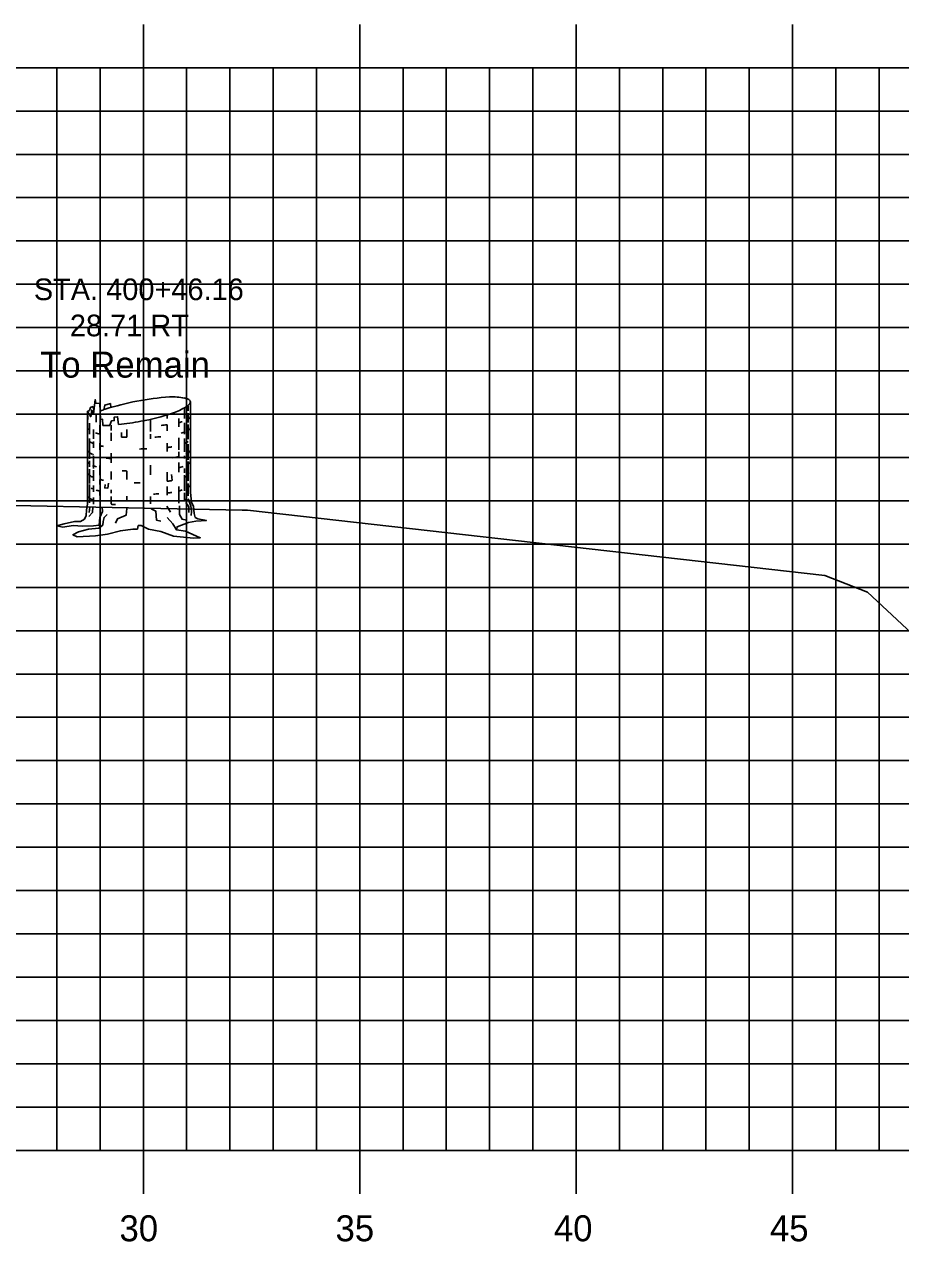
# Model space of a CAD drawing. Extents: x -161 to 764, y 111 to 210.
# Drawn here: x 181.42 to 201.67, y 125.06 to 153.17 of the extents above; entities that cross this region are included whole.
import ezdxf

# ---------------------------------------------------------------- set-up
doc = ezdxf.new("R2010")
doc.units = 0
for name, color, linetype in [('D_Text_Monospaced', 7, 'Continuous'), ('D_Text_Standard', 7, 'Continuous'), ('H_V ANNOTATION', 7, 'Continuous'), ('MAJOR', 7, 'Continuous'), ('MINOR', 7, 'Continuous'), ('S_Roadway_Centerline', 7, 'Continuous'), ('S_Trees_Decid_Pay', 7, 'Continuous')]:
    doc.layers.add(name, color=color, linetype=linetype)

msp = doc.modelspace()

# ---------------------------------------------------------------- linework, layer by layer
at = {"layer": 'MAJOR'}
for p, q in [((184.168, 153.171), (184.168, 152.169)), ((189.168, 153.171), (189.168, 152.169)), ((194.168, 153.171), (194.168, 152.169)), ((199.168, 153.171), (199.168, 152.169)), ((84.168, 152.169), (224.168, 152.169)), ((84.168, 152.169), (224.168, 152.169)), ((184.168, 127.169), (184.168, 152.169)), ((189.168, 127.169), (189.168, 152.169)), ((194.168, 127.169), (194.168, 152.169)), ((199.168, 127.169), (199.168, 152.169)), ((84.168, 147.169), (224.168, 147.169)), ((84.168, 142.169), (224.168, 142.169)), ((84.168, 137.169), (224.168, 137.169)), ((84.168, 132.169), (224.168, 132.169)), ((84.168, 127.169), (224.168, 127.169)), ((84.168, 127.169), (224.168, 127.169)), ((184.168, 126.167), (184.168, 127.169)), ((189.168, 126.167), (189.168, 127.169)), ((194.168, 126.167), (194.168, 127.169)), ((199.168, 126.167), (199.168, 127.169))]:
    msp.add_line(p, q, dxfattribs=at)
at = {"layer": 'MINOR'}
for p, q in [((182.168, 127.169), (182.168, 152.169)), ((183.168, 127.169), (183.168, 152.169)), ((185.168, 127.169), (185.168, 152.169)), ((186.168, 127.169), (186.168, 152.169)), ((187.168, 127.169), (187.168, 152.169)), ((188.168, 127.169), (188.168, 152.169)), ((190.168, 127.169), (190.168, 152.169)), ((191.168, 127.169), (191.168, 152.169)), ((192.168, 127.169), (192.168, 152.169)), ((193.168, 127.169), (193.168, 152.169)), ((195.168, 127.169), (195.168, 152.169)), ((196.168, 127.169), (196.168, 152.169)), ((197.168, 127.169), (197.168, 152.169)), ((198.168, 127.169), (198.168, 152.169)), ((200.168, 127.169), (200.168, 152.169)), ((201.168, 127.169), (201.168, 152.169)), ((84.168, 151.169), (224.168, 151.169)), ((84.168, 150.169), (224.168, 150.169)), ((84.168, 149.169), (224.168, 149.169)), ((84.168, 148.169), (224.168, 148.169)), ((84.168, 146.169), (224.168, 146.169)), ((84.168, 145.169), (224.168, 145.169)), ((84.168, 144.169), (224.168, 144.169)), ((84.168, 143.169), (224.168, 143.169)), ((84.168, 141.169), (224.168, 141.169)), ((84.168, 140.169), (224.168, 140.169)), ((84.168, 139.169), (224.168, 139.169)), ((84.168, 138.169), (224.168, 138.169)), ((84.168, 136.169), (224.168, 136.169)), ((84.168, 135.169), (224.168, 135.169)), ((84.168, 134.169), (224.168, 134.169)), ((84.168, 133.169), (224.168, 133.169)), ((84.168, 131.169), (224.168, 131.169)), ((84.168, 130.169), (224.168, 130.169)), ((84.168, 129.169), (224.168, 129.169)), ((84.168, 128.169), (224.168, 128.169))]:
    msp.add_line(p, q, dxfattribs=at)
at = {"layer": 'S_Roadway_Centerline'}
msp.add_lwpolyline([(152.685, 140.854), (168.169, 142.293), (172.399, 142.133), (178.178, 142.122), (186.449, 141.953), (186.572, 141.953), (199.915, 140.445), (200.903, 140.058), (203.287, 137.833), (209.093, 136.316), (210.852, 135.055), (224.168, 133.439)], dxfattribs=at)
at = {"layer": 'S_Trees_Decid_Pay'}
for p, q in [((185.121, 144.319), (185.121, 144.066)), ((185.201, 144.364), (185.201, 144.243)), ((182.927, 143.96), (182.927, 143.706)), ((183.077, 144.16), (183.077, 143.986)), ((184.333, 144.051), (184.333, 143.771)), ((184.716, 144.152), (184.716, 144.066)), ((184.989, 144.066), (184.989, 143.874)), ((185.121, 143.969), (185.121, 143.706)), ((185.201, 144.191), (185.201, 143.977)), ((185.201, 143.932), (185.201, 143.594)), ((183.013, 143.814), (183.013, 143.603)), ((183.161, 143.912), (183.161, 143.707)), ((183.422, 143.914), (183.422, 143.794)), ((183.422, 143.742), (183.422, 143.557)), ((183.661, 143.642), (183.666, 143.749)), ((183.787, 143.814), (183.787, 143.635)), ((184.333, 143.706), (184.333, 143.603)), ((184.716, 143.925), (184.716, 143.786)), ((182.927, 143.608), (182.927, 143.139)), ((183.013, 143.537), (183.013, 143.389)), ((183.161, 143.5), (183.161, 143.345)), ((184.716, 143.5), (184.716, 143.308)), ((184.989, 143.623), (184.989, 143.345)), ((185.121, 143.608), (185.121, 143.3)), ((185.201, 143.477), (185.201, 143.116)), ((182.927, 143.088), (182.927, 142.954)), ((183.013, 143.211), (183.013, 142.911)), ((183.422, 143.271), (183.422, 143.043)), ((184.989, 143.3), (184.989, 143.191)), ((185.121, 143.211), (185.121, 143.145)), ((182.927, 142.896), (182.927, 142.571)), ((183.013, 142.874), (183.013, 142.631)), ((183.161, 142.982), (183.161, 142.763)), ((183.422, 142.845), (183.422, 142.66)), ((183.787, 142.856), (183.787, 142.66)), ((184.333, 142.991), (184.333, 142.771)), ((184.716, 142.828), (184.716, 142.62)), ((184.989, 143.057), (184.989, 142.828)), ((185.121, 142.911), (185.121, 142.814)), ((185.201, 143.08), (185.201, 142.631)), ((182.927, 142.542), (182.927, 142.122)), ((183.161, 142.663), (183.161, 142.542)), ((185.121, 142.763), (185.121, 142.402)), ((185.201, 142.565), (185.201, 142.283)), ((183.013, 142.52), (183.013, 142.379)), ((183.013, 142.248), (183.013, 142.091)), ((183.161, 142.391), (183.161, 142.293)), ((183.422, 142.425), (183.422, 142.348)), ((183.422, 142.271), (183.422, 142.097)), ((183.787, 142.276), (183.787, 142.173)), ((184.333, 142.271), (184.333, 142.097)), ((184.716, 142.499), (184.716, 142.299)), ((184.989, 142.499), (184.989, 142.116)), ((185.121, 142.351), (185.121, 142.184)), ((182.93, 142.019), (182.916, 141.902)), ((184.712, 142.042), (184.792, 141.91))]:
    msp.add_line(p, q, dxfattribs=at)
for points in [[(183.233, 143.907), (183.225, 144.051), (183.18, 144.043), (183.165, 144.418), (183.071, 144.426), (183.056, 144.506), (183.019, 144.169), (182.974, 144.263), (182.953, 144.109), (182.876, 144.234), (182.882, 144.045)], [(182.876, 144.234), (182.876, 142.097), (182.856, 141.956), (182.85, 141.83), (182.807, 141.743), (182.714, 141.694), (182.579, 141.694), (182.335, 141.638), (182.168, 141.589), (182.311, 141.558), (182.548, 141.595), (182.758, 141.583), (183.019, 141.589), (183.143, 141.607), (183.173, 141.564), (183.235, 141.607), (183.136, 141.54), (182.901, 141.515), (182.671, 141.453), (182.541, 141.383), (182.64, 141.339), (183.062, 141.358), (183.34, 141.402), (183.639, 141.478), (183.925, 141.515), (184.03, 141.515), (184.048, 141.595), (184.117, 141.601), (184.283, 141.515), (184.569, 141.459), (184.868, 141.352), (185.327, 141.303), (185.481, 141.315), (185.14, 141.465), (184.936, 141.496), (184.948, 141.57), (185.208, 141.669), (185.383, 141.7), (185.624, 141.712), (185.426, 141.75), (185.364, 141.786), (185.34, 141.873), (185.327, 142.042), (185.282, 142.128), (185.254, 142.369), (185.254, 144.455)], [(182.876, 144.234), (182.922, 144.257), (182.945, 144.323), (182.997, 144.346), (183.03, 144.271)], [(183.255, 144.273), (183.276, 144.381), (183.408, 144.412), (183.415, 144.324)], [(183.394, 143.912), (183.431, 144.015), (183.497, 144.021), (183.497, 144.103), (183.571, 144.109), (183.596, 143.929)], [(183.285, 142.542), (183.276, 142.468), (183.35, 142.462), (183.365, 142.579)], [(184.83, 142.634), (184.829, 142.711), (184.821, 142.777)], [(182.997, 142.027), (182.99, 141.902), (182.908, 141.807)], [(183.143, 141.607), (183.161, 141.786), (183.223, 141.923), (183.216, 142.023)], [(183.785, 141.99), (183.768, 141.836), (183.571, 141.755), (183.525, 141.652)], [(184.351, 141.982), (184.454, 141.931), (184.468, 141.725), (184.571, 141.696)], [(185.006, 142.056), (185.006, 141.851), (185.063, 141.741), (185.161, 141.725)], [(185.146, 142.13), (185.218, 142.027), (185.218, 141.902)], [(185.203, 142.211), (185.264, 142.05), (185.277, 141.925), (185.27, 141.828)], [(183.334, 141.855), (183.26, 141.786), (183.241, 141.688), (183.235, 141.607)], [(184.936, 141.496), (184.85, 141.638), (184.718, 141.78)]]:
    msp.add_lwpolyline(points, dxfattribs=at)
for centre, radius, start, end in [((185.166, 138.453), 6.126, 93.6944, 100.7779), ((184.855, 143.27), 1.299, 78.2779, 93.6944), ((185.022, 144.073), 0.48, 69.9843, 78.2779), ((185.13, 144.369), 0.164, 55.7779, 69.9843), ((185.162, 144.416), 0.107, 45.9547, 55.7779), ((185.192, 144.447), 0.0645, 33.2779, 45.9547), ((183.686, 143.047), 1.299, 107.8613, 113.3069), ((185.166, 138.453), 6.126, 100.7779, 107.8613), ((184.445, 145.428), 1.299, 287.8613, 303.2779), ((184.894, 144.743), 0.48, 303.2779, 311.5714), ((185.104, 144.507), 0.164, 311.5714, 325.7779), ((185.151, 144.475), 0.107, 325.7779, 335.6011), ((185.2, 144.452), 0.0544, 22.46, 33.2779), ((185.19, 144.457), 0.0645, 335.6011, 348.2779), ((185.207, 144.455), 0.0467, 10.7779, 22.46), ((185.207, 144.455), 0.0467, 359.0957, 10.7779), ((185.199, 144.455), 0.0544, 348.2779, 359.0957), ((182.964, 150.022), 6.126, 275.9147, 280.7779), ((182.964, 150.022), 6.126, 280.7779, 287.8613), ((184.642, 145.217), 1.292, 285.5651, 289.0916), ((185.114, 144.198), 0.166, 301.67, 315), ((185.155, 144.157), 0.109, 315, 324.8263), ((185.19, 144.132), 0.0657, 324.8263, 337.5), ((185.2, 144.128), 0.0554, 337.5, 348.3185), ((182.924, 143.866), 0.0476, 180, 191.6815), ((182.932, 143.868), 0.0554, 191.6815, 202.5), ((182.941, 143.872), 0.0657, 202.5, 215.1737), ((182.977, 143.897), 0.109, 215.1737, 225), ((183.018, 143.937), 0.166, 225, 239.1924), ((183.489, 144.956), 1.292, 250.6119, 255.2856), ((183.275, 145.206), 1.299, 268.1289, 273.6944), ((182.964, 150.022), 6.126, 273.6944, 274.0246), ((184.065, 149.544), 5.916, 273.5382, 274.8924), ((184.066, 149.805), 5.916, 274.9514, 276.3087), ((184.641, 144.956), 1.292, 288.0829, 292.5), ((184.95, 144.21), 0.484, 297.4162, 300.8076), ((185.113, 143.937), 0.166, 300.8076, 315), ((185.154, 143.897), 0.109, 315, 324.8263), ((185.189, 143.872), 0.0657, 324.8263, 337.5), ((185.199, 143.868), 0.0554, 337.5, 348.3185), ((183.018, 143.674), 0.166, 237.0378, 239.1924), ((183.18, 143.947), 0.484, 239.1924, 247.5), ((183.489, 144.693), 1.292, 247.5, 248.3537), ((183.489, 144.693), 1.292, 255.2856, 259.2632), ((184.065, 149.544), 5.916, 266.0776, 267.3043), ((184.065, 149.281), 5.916, 270.1162, 271.7708), ((184.065, 149.281), 5.916, 276.3183, 277.1546), ((184.641, 144.693), 1.292, 277.1546, 278.3662), ((184.641, 144.693), 1.292, 291.8071, 292.5), ((184.95, 143.947), 0.484, 292.5, 300.8076), ((185.113, 143.674), 0.166, 300.8076, 301.6001), ((182.924, 143.345), 0.0476, 180, 191.6815), ((182.924, 143.088), 0.0476, 180, 191.6815), ((182.932, 143.347), 0.0554, 191.6815, 202.5), ((182.941, 143.351), 0.0657, 202.5, 215.1737), ((182.977, 143.376), 0.109, 215.1737, 225), ((183.018, 143.416), 0.166, 225, 239.1924), ((183.18, 143.689), 0.484, 239.1924, 245.7724), ((183.489, 144.435), 1.292, 247.5, 248.4842), ((183.489, 144.435), 1.292, 261.8726, 262.8454), ((184.065, 149.023), 5.916, 262.8454, 263.7595), ((184.641, 144.435), 1.292, 279.2565, 285.6105), ((184.95, 143.689), 0.484, 294.6372, 300.8076), ((185.113, 143.416), 0.166, 300.8076, 315), ((185.154, 143.376), 0.109, 315, 324.8263), ((185.189, 143.351), 0.0657, 324.8263, 337.5), ((185.199, 143.347), 0.0554, 337.5, 348.3185), ((182.924, 142.822), 0.0476, 180, 191.6815), ((182.932, 143.089), 0.0554, 191.6815, 202.5), ((182.932, 142.824), 0.0554, 191.6815, 202.5), ((182.941, 143.093), 0.0657, 202.5, 215.1737), ((182.941, 142.828), 0.0657, 202.5, 215.1737), ((182.977, 143.118), 0.109, 215.1737, 225), ((183.018, 143.159), 0.166, 225, 239.1924), ((183.489, 144.178), 1.292, 247.5, 251.799), ((184.065, 148.766), 5.916, 266.2721, 267.3043), ((184.641, 144.178), 1.292, 285.6105, 290.1001), ((185.113, 143.159), 0.166, 302.0694, 315), ((185.154, 143.118), 0.109, 315, 324.8263), ((185.189, 143.093), 0.0657, 324.8263, 337.5), ((185.199, 143.089), 0.0554, 337.5, 348.3185), ((185.199, 142.824), 0.0554, 337.5, 348.3185), ((182.977, 142.853), 0.109, 215.1737, 225), ((183.018, 142.893), 0.166, 225, 239.1924), ((183.18, 143.166), 0.484, 239.1924, 247.5), ((183.489, 143.913), 1.292, 247.5, 248.3537), ((183.489, 143.913), 1.292, 255.2856, 259.2463), ((184.065, 148.5), 5.916, 268.9206, 270), ((184.065, 148.5), 5.916, 270, 270.2757), ((184.065, 148.5), 5.916, 276.3183, 277.1546), ((184.641, 143.913), 1.292, 277.1546, 278.3795), ((184.95, 143.166), 0.484, 292.5, 300.8076), ((185.113, 142.893), 0.166, 300.8076, 302.0694), ((185.189, 142.556), 0.0657, 324.8263, 337.5), ((185.199, 142.552), 0.0554, 337.5, 348.3185), ((182.924, 142.293), 0.0476, 180, 191.6815), ((182.932, 142.295), 0.0554, 191.6815, 202.5), ((182.941, 142.299), 0.0657, 202.5, 215.1737), ((182.977, 142.324), 0.109, 215.1737, 225), ((183.018, 142.364), 0.166, 225, 239.1924), ((183.18, 142.894), 0.484, 242.734, 247.5), ((183.489, 143.641), 1.292, 251.3664, 255.2856), ((184.065, 148.229), 5.916, 273.2637, 274.461), ((184.065, 148.229), 5.916, 276.3183, 277.1546), ((184.641, 143.641), 1.292, 277.1546, 278.3662), ((184.641, 143.641), 1.292, 285.6105, 289.1534), ((185.113, 142.621), 0.166, 302.0694, 315), ((185.154, 142.581), 0.109, 315, 324.8263), ((183.18, 142.637), 0.484, 239.1924, 247.5), ((183.489, 143.383), 1.292, 247.5, 248.3537), ((184.065, 147.971), 5.916, 263.7831, 264.7655), ((184.65, 143.387), 1.292, 291.3696, 292.0604), ((184.95, 142.637), 0.484, 292.5, 296.5499)]:
    msp.add_arc(centre, radius, start, end, dxfattribs=at)

# ---------------------------------------------------------------- texts
at = {"layer": 'D_Text_Monospaced'}
for s, height, p in [('STA. 400+46.16', 0.49998, (181.637, 146.802)), ('28.71 RT', 0.5, (182.47, 145.968))]:
    msp.add_text(s, height=height, dxfattribs=at).set_placement(p)
at = {"layer": 'D_Text_Standard'}
msp.add_text('To Remain', height=0.6, dxfattribs=at).set_placement((181.782, 145.013))
at = {"layer": 'H_V ANNOTATION'}
for s, p in [('30', (183.616, 125.069)), ('35', (188.608, 125.069)), ('40', (193.654, 125.069)), ('45', (198.646, 125.069))]:
    msp.add_text(s, height=0.6, rotation=360, dxfattribs=at).set_placement(p)

doc.saveas('drawing.dxf')
